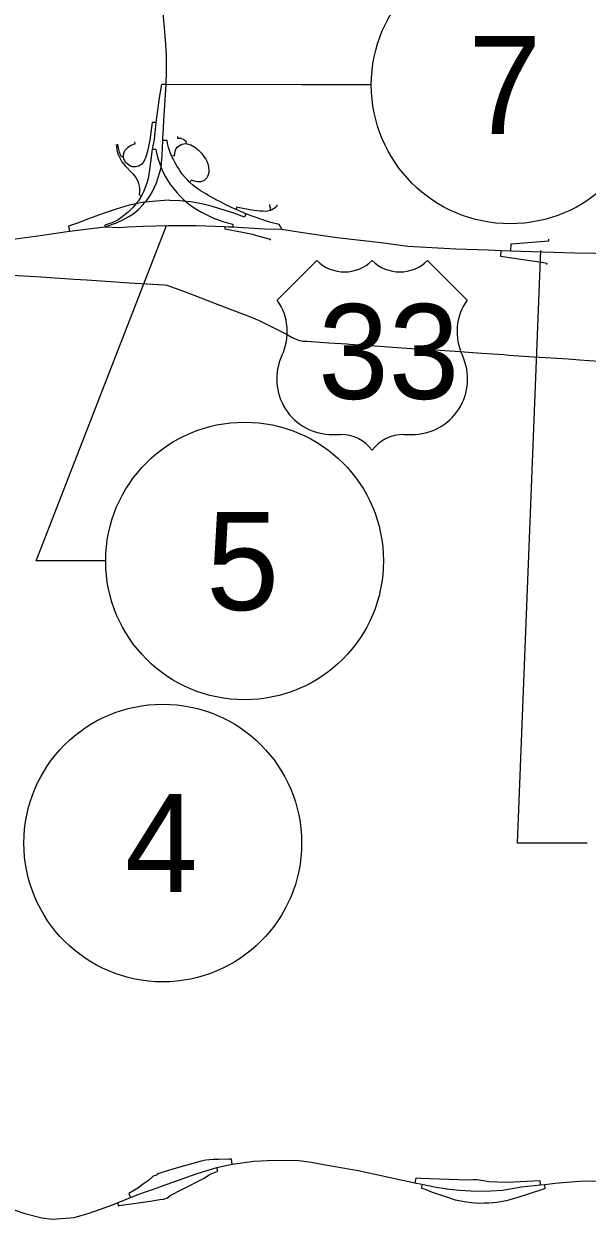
# Model space of a CAD drawing. Extents: x -1146 to -445, y -1283 to -822.
# Drawn here: x -877.16 to -856.5, y -1101.28 to -1057.42 of the extents above; entities that cross this region are included whole.
import ezdxf

# ---------------------------------------------------------------- set-up
doc = ezdxf.new("R2010")
doc.units = 0
for name, color, linetype in [('Default', 7, 'Continuous'), ('GM_X_Interchange_Ramps', 7, 'Continuous'), ('GM_X_Interstate_Route', 7, 'Continuous'), ('GM_X_State_Route', 7, 'Continuous'), ('GM_X_US_Route', 7, 'Continuous'), ('GM_X_US_Shield', 7, 'Continuous')]:
    doc.layers.add(name, color=color, linetype=linetype)

msp = doc.modelspace()

# ---------------------------------------------------------------- linework, layer by layer
at = {"layer": 'Default'}
for points in [[(-864.42, -1059.664), (-866.967, -1059.664), (-871.948, -1059.652)], [(-874.163, -1077.131), (-876.71, -1077.131), (-871.936, -1064.823)], [(-856.505, -1087.481), (-859.052, -1087.481), (-858.201, -1065.733)]]:
    msp.add_lwpolyline(points, dxfattribs=at)
for centre in [(-859.326, -1059.664), (-869.069, -1077.131), (-872.07, -1087.481)]:
    msp.add_circle(centre, 5.094, dxfattribs=at)
at = {"layer": 'GM_X_Interchange_Ramps'}
for points in [[(-871.948, -1059.652), (-872.118, -1059.65), (-872.202, -1060.135), (-872.289, -1060.778), (-872.324, -1061.043), (-872.389, -1061.663), (-872.454, -1062.016), (-872.483, -1062.215), (-872.557, -1062.774), (-872.612, -1063.1), (-872.655, -1063.266), (-872.71, -1063.426), (-872.76, -1063.561), (-872.833, -1063.702), (-872.956, -1063.911), (-873.055, -1064.028), (-873.153, -1064.145), (-873.343, -1064.335), (-873.715, -1064.626), (-873.937, -1064.722), (-874.196, -1064.804), (-874.195, -1064.869)], [(-872.324, -1061.043), (-872.457, -1061.041), (-872.542, -1061.686), (-872.624, -1062.038), (-872.645, -1062.139), (-872.669, -1062.232), (-872.706, -1062.343), (-872.735, -1062.414), (-872.777, -1062.496), (-872.841, -1062.569), (-872.911, -1062.62), (-872.992, -1062.655), (-873.065, -1062.67), (-873.184, -1062.665), (-873.259, -1062.643), (-873.42, -1062.523), (-873.472, -1062.439), (-873.495, -1062.374), (-873.507, -1062.3), (-873.505, -1062.22), (-873.486, -1062.141), (-873.456, -1062.075), (-873.403, -1062.003), (-873.345, -1061.949), (-873.276, -1061.901), (-873.194, -1061.858), (-873.139, -1061.837), (-873.083, -1061.821), (-873.092, -1061.749)], [(-867.698, -1064.958), (-867.804, -1064.79), (-868.101, -1064.709), (-868.215, -1064.674), (-868.307, -1064.645), (-868.39, -1064.618), (-868.484, -1064.587), (-868.574, -1064.556), (-868.714, -1064.506), (-868.859, -1064.452), (-868.912, -1064.433), (-869.019, -1064.389), (-869.124, -1064.347), (-869.267, -1064.287), (-869.392, -1064.233), (-869.595, -1064.138), (-869.728, -1064.075), (-869.842, -1064.018), (-869.958, -1063.958), (-870.082, -1063.893), (-870.196, -1063.831), (-870.355, -1063.741), (-870.492, -1063.66), (-870.656, -1063.561), (-870.771, -1063.487), (-870.875, -1063.413), (-870.983, -1063.326), (-871.093, -1063.226), (-871.169, -1063.149), (-871.235, -1063.078), (-871.354, -1062.933), (-871.444, -1062.806), (-871.497, -1062.722), (-871.551, -1062.63), (-871.612, -1062.526), (-871.694, -1062.372), (-871.723, -1062.311), (-871.745, -1062.264), (-871.794, -1062.147), (-871.824, -1062.064), (-871.86, -1061.954), (-871.887, -1061.858), (-871.911, -1061.702), (-872.069, -1061.702)], [(-871.532, -1061.561), (-871.533, -1061.617), (-871.411, -1061.622), (-871.296, -1061.667), (-871.208, -1061.738), (-871.22, -1061.813)], [(-873.782, -1061.85), (-873.769, -1061.933), (-873.756, -1062.027), (-873.739, -1062.107), (-873.714, -1062.193), (-873.686, -1062.268), (-873.651, -1062.344), (-873.612, -1062.417), (-873.566, -1062.488), (-873.511, -1062.562), (-873.444, -1062.637), (-873.168, -1062.931), (-873.099, -1063.008), (-873.042, -1063.089), (-872.99, -1063.189), (-872.956, -1063.283), (-872.933, -1063.379), (-872.923, -1063.475), (-872.924, -1063.573), (-872.939, -1063.696), (-872.833, -1063.702)], [(-873.507, -1062.3), (-873.589, -1062.298), (-873.611, -1062.255), (-873.634, -1062.202), (-873.658, -1062.134), (-873.673, -1062.083), (-873.684, -1062.034), (-873.693, -1061.985), (-873.709, -1061.926), (-873.717, -1061.841)], [(-872.454, -1062.016), (-872.32, -1062.024), (-872.295, -1062.173), (-872.239, -1062.391), (-872.169, -1062.598), (-872.127, -1062.699), (-872.064, -1062.851), (-871.982, -1063.011), (-871.894, -1063.162), (-871.786, -1063.324), (-871.67, -1063.48), (-871.559, -1063.612), (-871.435, -1063.745), (-871.307, -1063.867), (-871.22, -1063.94), (-871.14, -1064.009), (-870.986, -1064.124), (-870.8, -1064.245), (-870.652, -1064.33), (-870.427, -1064.446), (-870.239, -1064.534), (-870.034, -1064.617), (-869.869, -1064.675), (-869.692, -1064.729), (-869.5, -1064.776), (-869.494, -1064.778), (-869.502, -1064.876)], [(-871.719, -1062.258), (-871.646, -1062.262), (-871.62, -1062.096), (-871.576, -1061.994), (-871.542, -1061.949), (-871.495, -1061.913), (-871.437, -1061.868), (-871.374, -1061.839), (-871.301, -1061.824), (-871.22, -1061.813), (-871.129, -1061.831), (-871.037, -1061.863), (-870.891, -1061.949), (-870.771, -1062.041), (-870.637, -1062.185), (-870.589, -1062.249), (-870.541, -1062.325), (-870.491, -1062.391), (-870.459, -1062.465), (-870.421, -1062.558), (-870.405, -1062.612), (-870.392, -1062.679), (-870.378, -1062.796), (-870.38, -1062.875), (-870.401, -1062.963), (-870.43, -1063.026), (-870.455, -1063.069), (-870.488, -1063.11), (-870.518, -1063.137), (-870.562, -1063.177), (-870.612, -1063.198), (-870.662, -1063.213), (-870.795, -1063.222), (-870.923, -1063.2), (-871.02, -1063.152), (-871.093, -1063.226)], [(-869.019, -1064.389), (-869.071, -1064.518), (-869.458, -1064.374), (-869.821, -1064.26), (-870.245, -1064.124), (-870.632, -1064.025), (-871.048, -1063.957), (-871.22, -1063.94), (-871.434, -1063.919), (-871.815, -1063.899), (-871.858, -1063.897), (-872.298, -1063.927), (-872.723, -1063.97), (-872.82, -1063.98), (-873.055, -1064.028), (-873.297, -1064.079), (-873.782, -1064.222), (-874.251, -1064.382), (-874.789, -1064.579), (-875.198, -1064.738), (-875.523, -1064.851), (-875.497, -1065.029)], [(-867.883, -1064.057), (-867.886, -1064.109), (-867.934, -1064.157), (-867.988, -1064.199), (-868.051, -1064.236), (-868.124, -1064.27), (-868.179, -1064.285), (-868.235, -1064.297), (-868.3, -1064.303), (-868.382, -1064.301), (-868.514, -1064.296), (-868.609, -1064.288), (-868.733, -1064.274), (-868.874, -1064.252), (-869.002, -1064.227), (-869.13, -1064.195), (-869.355, -1064.152), (-869.392, -1064.233)], [(-868.154, -1064.048), (-868.157, -1064.113), (-868.152, -1064.117), (-868.14, -1064.132), (-868.132, -1064.147), (-868.127, -1064.16), (-868.124, -1064.182), (-868.127, -1064.204), (-868.137, -1064.229), (-868.124, -1064.27)], [(-869.793, -1064.861), (-869.799, -1064.946), (-869.141, -1065.06), (-868.776, -1065.144), (-868.627, -1065.187), (-868.128, -1065.319), (-868.128, -1065.363)], [(-857.919, -1065.323), (-857.922, -1065.393), (-859.274, -1065.508), (-859.304, -1065.508), (-859.312, -1065.748)], [(-859.67, -1065.737), (-859.676, -1065.941), (-858.108, -1066.178), (-857.986, -1066.201), (-857.988, -1066.255)], [(-869.526, -1099.26), (-869.545, -1099.082), (-869.65, -1099.082), (-870.025, -1099.088), (-870.218, -1099.095), (-870.352, -1099.103), (-870.489, -1099.121), (-870.667, -1099.158), (-871.574, -1099.412), (-872.259, -1099.621), (-872.298, -1099.669)], [(-871.898, -1100.496), (-871.798, -1100.416), (-871.372, -1100.189), (-870.557, -1099.78), (-870.357, -1099.643), (-870.178, -1099.569), (-870.051, -1099.525), (-870.086, -1099.391)], [(-872.298, -1099.669), (-872.42, -1099.706), (-872.599, -1099.864), (-872.772, -1099.988), (-872.985, -1100.139), (-873.172, -1100.256), (-873.313, -1100.337), (-873.253, -1100.486)], [(-860.533, -1099.841), (-860.692, -1099.838), (-860.879, -1099.849), (-862.599, -1099.794), (-862.787, -1099.78), (-862.788, -1099.78), (-862.821, -1099.945)], [(-858.215, -1100.026), (-858.23, -1099.871), (-859.446, -1099.937), (-859.794, -1099.924), (-860.095, -1099.906), (-860.449, -1099.849), (-860.533, -1099.841)], [(-862.562, -1099.994), (-862.582, -1100.146), (-862.443, -1100.185), (-862.189, -1100.295), (-861.741, -1100.44), (-861.342, -1100.57), (-861.139, -1100.611), (-860.925, -1100.64), (-860.74, -1100.666), (-860.598, -1100.68)], [(-860.598, -1100.68), (-860.491, -1100.689), (-860.286, -1100.68), (-860.104, -1100.68), (-859.817, -1100.657), (-859.459, -1100.591), (-859.074, -1100.486), (-858.091, -1100.171), (-858.038, -1100.16), (-858.051, -1100.006)], [(-873.732, -1100.681), (-873.689, -1100.787), (-873.671, -1100.784), (-872.534, -1100.617), (-872.179, -1100.564), (-872.043, -1100.544), (-871.898, -1100.496)]]:
    msp.add_lwpolyline(points, dxfattribs=at)
at = {"layer": 'GM_X_Interstate_Route'}
for points in [[(-872.045, -1061.245), (-872.03, -1060.969), (-871.948, -1059.652), (-871.929, -1059.206), (-871.934, -1058.568), (-871.973, -1058.011), (-872.016, -1057.437), (-872.031, -1057.3), (-872.047, -1057.158), (-872.184, -1055.956)], [(-872.065, -1061.612), (-872.045, -1061.245)], [(-872.741, -1063.991), (-872.723, -1063.97), (-872.672, -1063.911), (-872.535, -1063.716), (-872.444, -1063.576), (-872.295, -1063.255), (-872.176, -1062.869), (-872.127, -1062.699), (-872.123, -1062.685), (-872.093, -1062.246), (-872.069, -1061.702)], [(-872.069, -1061.702), (-872.065, -1061.612)], [(-874.195, -1064.869), (-873.764, -1064.722), (-873.53, -1064.615), (-873.316, -1064.493), (-873.162, -1064.387), (-872.966, -1064.229), (-872.803, -1064.063), (-872.741, -1063.991)], [(-877.844, -1065.363), (-876.737, -1065.211), (-875.497, -1065.029)], [(-875.497, -1065.029), (-874.195, -1064.869)], [(-874.195, -1064.869), (-873.641, -1064.889), (-873.364, -1064.867), (-872.793, -1064.84), (-871.862, -1064.821), (-870.851, -1064.823), (-869.793, -1064.861), (-869.676, -1064.867)], [(-869.676, -1064.867), (-869.502, -1064.876), (-868.343, -1064.938), (-867.698, -1064.958), (-867.022, -1065.071), (-865.683, -1065.265), (-864.06, -1065.444), (-863.075, -1065.58), (-861.315, -1065.675), (-860.131, -1065.719), (-859.67, -1065.737), (-859.312, -1065.748), (-856.96, -1065.825), (-855.462, -1065.843), (-853.717, -1065.957), (-853.262, -1065.982), (-851.494, -1066.091), (-848.831, -1066.296), (-847.742, -1066.389), (-847.546, -1066.422), (-847.131, -1066.539), (-846.894, -1066.633), (-846.756, -1066.698)]]:
    msp.add_lwpolyline(points, dxfattribs=at)
at = {"layer": 'GM_X_State_Route'}
for points in [[(-872.245, -1100.114), (-872.118, -1100.07), (-870.814, -1099.601), (-870.408, -1099.48), (-870.086, -1099.391), (-869.526, -1099.26), (-868.725, -1099.158), (-867.977, -1099.113), (-867.073, -1099.132), (-866.615, -1099.184), (-866.312, -1099.248), (-864.905, -1099.5), (-862.821, -1099.945), (-862.562, -1099.994), (-862.037, -1100.103), (-861.712, -1100.158)], [(-881.174, -1099.842), (-880.451, -1099.923), (-880.119, -1099.948), (-879.858, -1099.988), (-879.598, -1100.056), (-879.133, -1100.231), (-879.006, -1100.285), (-878.484, -1100.52), (-878.115, -1100.664), (-877.755, -1100.828), (-877.489, -1100.946), (-877.127, -1101.069), (-876.502, -1101.23), (-876.124, -1101.279), (-875.315, -1101.221), (-874.77, -1101.06), (-874.015, -1100.797), (-873.732, -1100.681), (-873.253, -1100.486), (-872.912, -1100.347), (-872.245, -1100.114)], [(-861.712, -1100.158), (-861.669, -1100.165), (-861.183, -1100.223), (-860.564, -1100.258), (-860.037, -1100.246), (-859.606, -1100.217), (-858.905, -1100.098), (-858.215, -1100.026), (-858.051, -1100.006), (-857.68, -1099.962), (-857.249, -1099.927), (-856.774, -1099.893), (-855.932, -1099.879)]]:
    msp.add_lwpolyline(points, dxfattribs=at)
at = {"layer": 'GM_X_US_Route'}
msp.add_lwpolyline([(-877.82, -1066.626), (-876.53, -1066.706), (-875.315, -1066.791), (-874.859, -1066.813), (-873.805, -1066.884), (-873.292, -1066.919), (-872.019, -1067.001), (-871.917, -1067.016), (-871.311, -1067.233), (-870.897, -1067.394), (-870.076, -1067.709), (-869.241, -1068.028), (-868.948, -1068.14), (-868.679, -1068.247), (-868.529, -1068.305), (-867.874, -1068.637), (-867.552, -1068.802), (-867.318, -1068.926), (-867.097, -1069.028), (-866.934, -1069.061), (-866.791, -1069.071), (-865.979, -1069.126), (-865.303, -1069.165), (-865.22, -1069.17), (-864.282, -1069.241), (-863.303, -1069.304), (-862.405, -1069.369), (-861.908, -1069.399), (-861.346, -1069.438), (-860.367, -1069.501), (-859.56, -1069.56), (-859.373, -1069.573), (-858.825, -1069.611), (-858.462, -1069.636), (-857.618, -1069.688), (-857.203, -1069.716), (-856.78, -1069.746), (-855.72, -1069.824)], dxfattribs=at)
at = {"layer": 'GM_X_US_Shield'}
for p, q in [((-866.419, -1066.108), (-867.87, -1067.558)), ((-860.909, -1067.558), (-862.359, -1066.108)), ((-865.839, -1072.489), (-865.549, -1072.489)), ((-863.229, -1072.489), (-862.939, -1072.489))]:
    msp.add_line(p, q, dxfattribs=at)
for centre, radius, start, end in [((-865.404, -1065.072), 1.45, 225.573, 314.427), ((-863.374, -1065.072), 1.45, 225.573, 314.427), ((-869.533, -1068.722), 2.03, 334.5471, 35.0009), ((-859.245, -1068.722), 2.03, 144.9991, 205.4529), ((-865.862, -1070.458), 2.03, 154.8319, 270.6383), ((-862.916, -1070.458), 2.03, 269.3617, 25.1681), ((-865.549, -1073.939), 1.45, 36.8699, 90), ((-863.229, -1073.939), 1.45, 90, 143.1301)]:
    msp.add_arc(centre, radius, start, end, dxfattribs=at)

# ---------------------------------------------------------------- texts
at = {"layer": 'Default'}
for s, p in [('7', (-860.859, -1061.464)), ('5', (-870.478, -1078.931)), ('4', (-873.459, -1089.281))]:
    msp.add_text(s, height=3.6, dxfattribs=at).set_placement(p)
at = {"layer": 'GM_X_US_Shield'}
msp.add_text('33', height=3.4805, dxfattribs=at).set_placement((-866.37, -1071.183))

doc.saveas('drawing.dxf')
